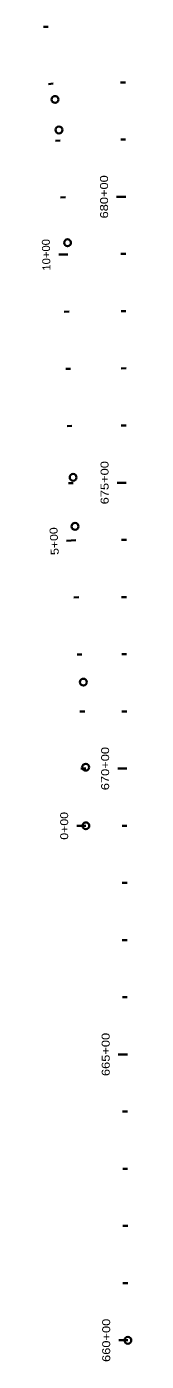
# Model space of a CAD drawing. Extents: x 2357892 to 2370172, y 6966790 to 6985499.
# Drawn here: x 2364275 to 2364432, y 6966790 to 6969124 of the extents above; entities that cross this region are included whole.
import ezdxf
from ezdxf.enums import TextEntityAlignment as Align

# ---------------------------------------------------------------- set-up
doc = ezdxf.new("R2010")
doc.units = 0
doc.header["$LTSCALE"] = 5.6
doc.layers.add('28', color=7, linetype='Continuous', lineweight=35)

msp = doc.modelspace()

# ---------------------------------------------------------------- linework, layer by layer
at = {"layer": '28'}
for p, q in [((2364286.27, 6969124.074), (2364277.785, 6969123.559)), ((2364294.935, 6969024.461), (2364286.489, 6969023.503)), ((2364421.789, 6969026.545), (2364413.289, 6969026.529)), ((2364307.364, 6968925.237), (2364298.923, 6968924.237)), ((2364421.98, 6968926.545), (2364413.48, 6968926.529)), ((2364316.526, 6968825.67), (2364308.044, 6968825.113)), ((2364422.17, 6968826.545), (2364406.17, 6968826.515)), ((2364320.573, 6968725.761), (2364304.578, 6968725.378)), ((2364422.36, 6968726.546), (2364413.86, 6968726.529)), ((2364322.964, 6968625.789), (2364314.466, 6968625.586)), ((2364422.55, 6968626.546), (2364414.05, 6968626.53)), ((2364325.354, 6968525.818), (2364316.856, 6968525.615)), ((2364422.74, 6968526.546), (2364414.24, 6968526.53)), ((2364327.744, 6968425.846), (2364319.247, 6968425.643)), ((2364422.93, 6968426.546), (2364414.43, 6968426.53)), ((2364330.152, 6968325.875), (2364321.655, 6968325.643)), ((2364423.12, 6968326.546), (2364407.12, 6968326.516)), ((2364334.532, 6968225.975), (2364318.555, 6968225.114)), ((2364423.31, 6968226.546), (2364414.81, 6968226.53)), ((2364339.915, 6968126.12), (2364331.427, 6968125.663)), ((2364423.5, 6968126.547), (2364415, 6968126.53)), ((2364345.297, 6968026.265), (2364336.81, 6968025.808)), ((2364423.69, 6968026.547), (2364415.19, 6968026.531)), ((2364350.221, 6967926.388), (2364341.727, 6967926.083)), ((2364423.88, 6967926.547), (2364415.38, 6967926.531)), ((2364352.07, 6967826.41), (2364343.57, 6967826.394)), ((2364424.07, 6967826.547), (2364408.07, 6967826.517)), ((2364352.26, 6967726.411), (2364336.261, 6967726.38)), ((2364424.26, 6967726.547), (2364415.76, 6967726.531)), ((2364424.45, 6967626.548), (2364415.95, 6967626.531)), ((2364424.641, 6967526.548), (2364416.141, 6967526.532)), ((2364424.831, 6967426.548), (2364416.331, 6967426.532)), ((2364425.021, 6967326.548), (2364409.021, 6967326.518)), ((2364425.211, 6967226.548), (2364416.711, 6967226.532)), ((2364425.401, 6967126.548), (2364416.901, 6967126.532)), ((2364425.591, 6967026.549), (2364417.091, 6967026.532)), ((2364425.781, 6966926.549), (2364417.281, 6966926.533)), ((2364425.971, 6966826.549), (2364409.971, 6966826.519))]:
    msp.add_line(p, q, dxfattribs=at)
for centre in [(2364298.274, 6968996.826), (2364305.122, 6968943.414), (2364320.085, 6968746.169), (2364329.896, 6968335.836), (2364333.231, 6968250.107), (2364347.918, 6967977.66), (2364352.066, 6967828.899), (2364352.26, 6967726.411), (2364425.971, 6966826.549)]:
    msp.add_circle(centre, 6, dxfattribs=at)

# ---------------------------------------------------------------- texts
for s, rotation, width, p in [('680+00', 90.109, 1.2, (2364391.17, 6968826.5)), ('10+00', 91.37, 1.05, (2364289.578, 6968725.188)), ('675+00', 90.109, 1.2, (2364392.12, 6968326.5)), ('5+00', 93.086, 1.15, (2364303.556, 6968224.684)), ('670+00', 90.109, 1.2, (2364393.071, 6967826.501)), ('0+00', 90.109, 1.15, (2364321.261, 6967726.366)), ('665+00', 90.109, 1.2, (2364394.02, 6967326.502)), ('660+00', 90.109, 1.2, (2364394.971, 6966826.503))]:
    msp.add_text(s, height=14, rotation=rotation, dxfattribs=dict(at, width=width)).set_placement(p, align=Align.CENTER)

doc.saveas('drawing.dxf')
